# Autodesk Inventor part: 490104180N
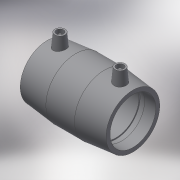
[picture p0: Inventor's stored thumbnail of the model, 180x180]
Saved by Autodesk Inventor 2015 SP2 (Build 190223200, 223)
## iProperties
Created: 2017-06
Part Number: 490104180N
Material: Generic
Description: PLASSON COUPLER 180-180
Document SubType Name: Modeling
Designer: KIM
Mass: 2057.46 g
Surface Area: 2870.26 cm^2
Volume: 2057.46 cm^3
Density: 1 g/cm^3
Appearance: Default
Author: KIM
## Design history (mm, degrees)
derived "490104.ipt"
feature "Solid1::490104.ipt"
tag "TaggingFeature1"
body "Solid1"
other parameters: "d0" = 212, "d2" = 218, "d3" = 105, "d4" = 70.66667, "d5" = 196.2, "d6" = 171, "d8" = 168 deg, "d10" = 42, "d11" = 14, "d13" = 212, "d14" = 17.6296, "d15" = 105, "d16" = 105, "d17" = 171, "d19" = 3.52592, "d20" = 168 deg, "d22" = 204.92, "d23" = 218, "d24" = 198.7724, "d25" = 135 deg, "d26" = 106, "d27" = 135 deg, "d29" = 116, "d30" = 14, "d31" = 74.2, "d34" = 5 deg, "d35" = 15, "d39" = 5 deg, "d41" = 4, "d42" = 14, "d43" = 0, "d45" = 4, "d46" = 14, "d47" = 0, "d48" = 3, "d49" = 0, "d50" = 3, "d51" = 0, "d52" = 30.45, "d53" = 7.6125, "L_" = 212, "L_1" = 105, "D_" = 218, "A_" = 116, "d_2" = 12
